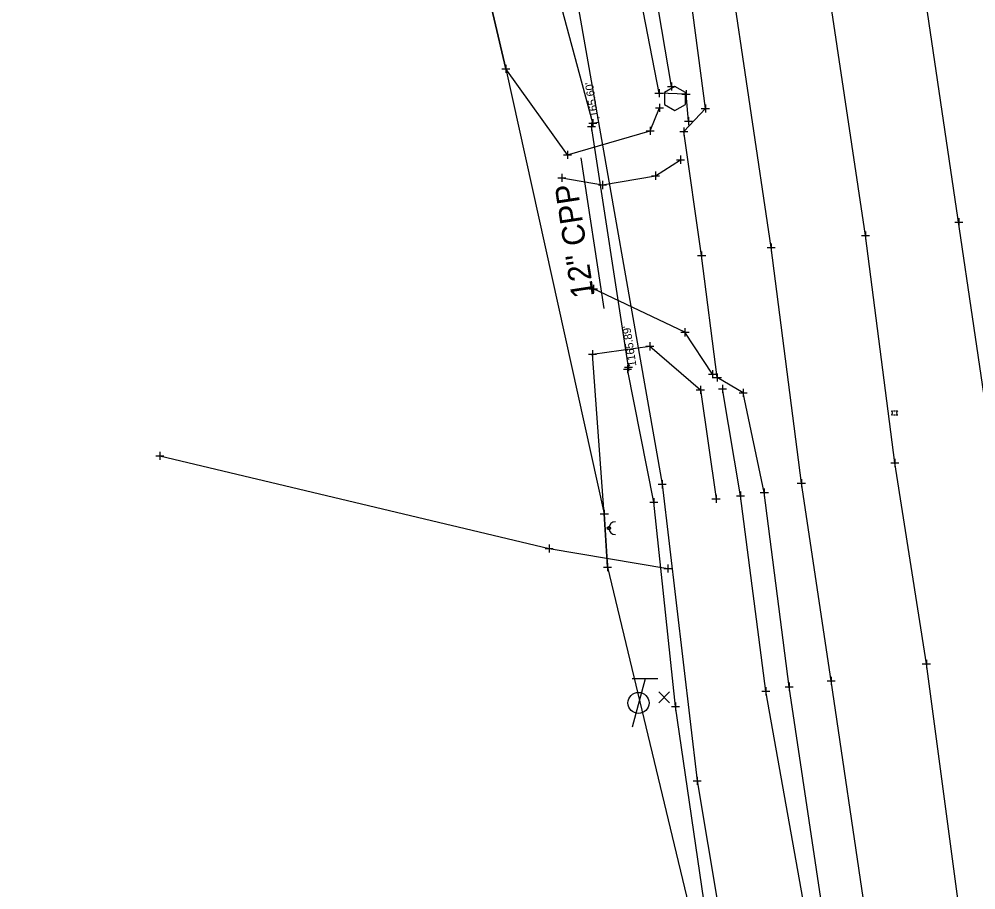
# Model space of a CAD drawing. Extents: x 2324380 to 2325559, y 691096 to 693386.
# Drawn here: x 2325087.6 to 2325205.9, y 691550.8 to 691658.5 of the extents above; entities that cross this region are included whole.
import ezdxf

# ---------------------------------------------------------------- set-up
doc = ezdxf.new("R2010")
doc.units = 0
for name, color, linetype in [('DR_X_Elev_Flow', 7, 'Continuous'), ('DR_X_Storm_Sewer', 7, 'Continuous'), ('DR_X_Text', 7, 'Continuous'), ('PM_X_Cells', 7, 'Continuous'), ('PM_X_CL_Double_Solid', 7, 'Continuous'), ('PM_X_Transverse_Line', 7, 'Continuous'), ('PV_X_COP', 7, 'Continuous'), ('PV_X_Driveway', 7, 'Continuous'), ('PV_X_EOP', 7, 'Continuous'), ('PV_X_Shoulder_Aggregate', 7, 'Continuous'), ('RD_X_Cells', 7, 'Continuous'), ('RD_X_GR_Lt', 7, 'Continuous'), ('SC_Scratch1', 7, 'Continuous'), ('SV_X_Random_Point', 7, 'Continuous'), ('SV_X_Shot_Marker', 7, 'Continuous'), ('SV_X_Terrain_Boundary', 7, 'Continuous'), ('SV_X_Toe_of_Slope', 7, 'Continuous'), ('SV_X_Top_of_Bank', 7, 'Continuous'), ('UT_X_Gas', 7, 'Continuous'), ('UT_X_Misc_Cells', 7, 'Continuous'), ('UT_X_Telecom_Cells', 7, 'Continuous')]:
    doc.layers.add(name, color=color, linetype=linetype)

msp = doc.modelspace()

# ---------------------------------------------------------------- linework, layer by layer
at = {"layer": 'DR_X_Elev_Flow'}
for p, q in [((2325157.91, 691645.2), (2325158.91, 691645.2)), ((2325158.41, 691645.7), (2325158.41, 691644.7)), ((2325158.41, 691645.2), (2325158.41, 691645.2)), ((2325162.97, 691615.95), (2325162.97, 691614.95)), ((2325162.47, 691615.45), (2325163.47, 691615.45)), ((2325162.97, 691615.45), (2325162.97, 691615.45))]:
    msp.add_line(p, q, dxfattribs=at)
at = {"layer": 'DR_X_Storm_Sewer'}
msp.add_line((2325162.97, 691615.45), (2325158.41, 691645.2), dxfattribs=at)
at = {"layer": 'DR_X_Text'}
msp.add_line((2325157.08, 691641.34), (2325159.94, 691622.69), dxfattribs=at)
at = {"layer": 'PM_X_Cells'}
for p, q in [((2325195.49, 691610.02), (2325195.59, 691610.02)), ((2325195.66, 691610.02), (2325195.76, 691610.02)), ((2325195.83, 691610.02), (2325195.93, 691610.02)), ((2325195.88, 691609.78), (2325195.88, 691609.78)), ((2325196, 691610.02), (2325196.1, 691610.02)), ((2325196.16, 691610.02), (2325196.26, 691610.02)), ((2325195.49, 691609.53), (2325195.59, 691609.53)), ((2325195.66, 691609.53), (2325195.76, 691609.53)), ((2325195.83, 691609.53), (2325195.93, 691609.53)), ((2325196, 691609.53), (2325196.1, 691609.53)), ((2325196.16, 691609.53), (2325196.26, 691609.53))]:
    msp.add_line(p, q, dxfattribs=at)
for centre, start, end in [((2325195.34, 691609.78), 42.0847, 58.0262), ((2325195.34, 691609.78), 301.9738, 317.9205), ((2325195.34, 691609.78), 18.8878, 34.8207), ((2325195.34, 691609.78), 325.1782, 341.1111), ((2325195.34, 691609.78), 348.3904, 11.6202), ((2325196.42, 691609.78), 168.3816, 191.6091), ((2325196.42, 691609.78), 145.1782, 161.1098), ((2325196.42, 691609.78), 198.8872, 214.8207), ((2325196.42, 691609.78), 121.9738, 137.9163), ((2325196.42, 691609.78), 222.0817, 238.0262)]:
    msp.add_arc(centre, 0.288, start, end, dxfattribs=at)
at = {"layer": 'PM_X_CL_Double_Solid'}
msp.add_lwpolyline([(2325203.69, 691549.65), (2325199.81, 691578.72), (2325195.9, 691603.62), (2325192.28, 691631.74), (2325187.11, 691666.48), (2325182.79, 691692.39), (2325178.74, 691718.23), (2325173.96, 691747.27), (2325169.08, 691775.55), (2325163.39, 691807.62), (2325158.37, 691834.22), (2325153.07, 691860.53), (2325147.82, 691885.48), (2325142.33, 691910.37), (2325135.95, 691937.62), (2325128.86, 691967.59), (2325122.12, 691994.31), (2325114.33, 692023.68), (2325108.45, 692046.03), (2325104.94, 692058.15)], dxfattribs=at)
at = {"layer": 'PM_X_Transverse_Line'}
for points in [[(2325208.03, 691604.62), (2325194.77, 691694.59), (2325190.22, 691721.35), (2325186.04, 691748.47), (2325180.66, 691777.72), (2325175.44, 691810.81), (2325170.12, 691836.61), (2325164.91, 691862.73), (2325159.59, 691887.99), (2325154.32, 691913.69), (2325148, 691940.38), (2325141.01, 691970.75), (2325134.25, 691997.6), (2325126.61, 692026.24), (2325119.99, 692049.57), (2325112.24, 692077.64)], [(2325192.19, 691548.44), (2325188.05, 691576.64), (2325184.35, 691601.09), (2325180.61, 691630.23), (2325175.41, 691665.27), (2325167.04, 691716.76), (2325162.47, 691745.62), (2325157.37, 691774.04), (2325151.47, 691805.52), (2325146.76, 691831.27), (2325141.02, 691858.38), (2325136.15, 691882.66), (2325130.6, 691908), (2325124.67, 691934.37), (2325117.5, 691964.78), (2325110.75, 691991.5), (2325102.89, 692021.66), (2325098.58, 692037.21)]]:
    msp.add_lwpolyline(points, dxfattribs=at)
at = {"layer": 'PV_X_COP'}
msp.add_lwpolyline([(2325203.69, 691549.65), (2325199.81, 691578.72), (2325195.9, 691603.62), (2325192.28, 691631.74), (2325187.11, 691666.48), (2325182.79, 691692.39), (2325178.74, 691718.23), (2325173.96, 691747.27), (2325169.08, 691775.55), (2325163.39, 691807.62), (2325158.37, 691834.22), (2325153.07, 691860.53), (2325147.82, 691885.48), (2325142.33, 691910.37), (2325135.95, 691937.62), (2325128.86, 691967.59), (2325122.12, 691994.31), (2325114.33, 692023.68), (2325108.45, 692046.03), (2325099.34, 692075.66)], dxfattribs=at)
at = {"layer": 'PV_X_Driveway'}
for points in [[(2325154.73, 691638.85), (2325159.77, 691637.98), (2325166.32, 691639.13), (2325169.41, 691641.11)], [(2325173.37, 691614.57), (2325169.96, 691619.75), (2325158.63, 691625.14)]]:
    msp.add_lwpolyline(points, dxfattribs=at)
at = {"layer": 'PV_X_EOP'}
for p, q in [((2325172.48, 691647.45), (2325170.28, 691664.36)), ((2325169.81, 691644.61), (2325172.48, 691647.45)), ((2325172.02, 691629.24), (2325169.81, 691644.61)), ((2325173.96, 691614.17), (2325172.02, 691629.24)), ((2325177.16, 691612.27), (2325173.96, 691614.17)), ((2325179.77, 691599.94), (2325177.16, 691612.27)), ((2325182.84, 691575.91), (2325179.77, 691599.94)), ((2325187.12, 691547.4), (2325182.84, 691575.91))]:
    msp.add_line(p, q, dxfattribs=at)
at = {"layer": 'PV_X_Shoulder_Aggregate'}
for points in [[(2325170.4, 691645.86), (2325170.09, 691649.23), (2325166.75, 691649.33), (2325163.95, 691663.81), (2325159.46, 691688.82), (2325155.24, 691715.43), (2325150.26, 691742.78), (2325145.57, 691771.72), (2325140.06, 691803.19), (2325135.21, 691830.02), (2325129.98, 691855.68), (2325124.5, 691880.26), (2325119.34, 691905.48), (2325112.99, 691932.07), (2325105.49, 691961.94), (2325098.55, 691989.12), (2325091.91, 692018.77), (2325090.18, 692026), (2325093.94, 692028.55)], [(2325216.93, 691320.12), (2325213.13, 691346.45), (2325209.2, 691372.56), (2325204.44, 691403.48), (2325200.05, 691432.7), (2325196.09, 691464.3), (2325192.26, 691490.46), (2325188.82, 691516.64), (2325184.99, 691547.18), (2325179.95, 691575.34), (2325176.82, 691599.54), (2325174.6, 691612.75)]]:
    msp.add_lwpolyline(points, dxfattribs=at)
at = {"layer": 'RD_X_Cells'}
msp.add_lwpolyline([(2325167.41, 691647.93), (2325168.71, 691647.18), (2325170.01, 691647.93), (2325170.01, 691649.43), (2325168.71, 691650.18), (2325167.41, 691649.43), (2325167.41, 691647.93)], dxfattribs=at)
at = {"layer": 'RD_X_GR_Lt'}
msp.add_lwpolyline([(2325168.31, 691650.15), (2325165.91, 691664.32), (2325160.24, 691688.12), (2325157.53, 691715.74), (2325153.07, 691743.32), (2325148.21, 691772.69), (2325142.47, 691803.42), (2325137.57, 691830.35), (2325132.48, 691855.68), (2325127.08, 691880.89), (2325121.34, 691906.57), (2325115.7, 691932.5), (2325101.27, 691989.61), (2325092.98, 692018.84), (2325091.76, 692024.72)], dxfattribs=at)
at = {"layer": 'SV_X_Random_Point'}
for p, q in [((2325166.72, 691573.93), (2325168.06, 691575.26)), ((2325166.72, 691575.26), (2325168.06, 691573.93))]:
    msp.add_line(p, q, dxfattribs=at)
at = {"layer": 'SV_X_Shot_Marker'}
for p, q in [((2325147.29, 691652.35), (2325148.29, 691652.35)), ((2325147.79, 691652.85), (2325147.79, 691651.85)), ((2325147.79, 691652.35), (2325147.79, 691652.35)), ((2325166.75, 691649.83), (2325166.75, 691648.83)), ((2325167.81, 691650.15), (2325168.81, 691650.15)), ((2325168.31, 691650.65), (2325168.31, 691649.65)), ((2325168.31, 691650.15), (2325168.31, 691650.15)), ((2325166.25, 691649.33), (2325167.25, 691649.33)), ((2325166.75, 691649.33), (2325166.75, 691649.33)), ((2325169.59, 691649.23), (2325170.59, 691649.23)), ((2325170.09, 691649.73), (2325170.09, 691648.73)), ((2325170.09, 691649.23), (2325170.09, 691649.23)), ((2325166.32, 691647.53), (2325167.32, 691647.53)), ((2325166.82, 691648.03), (2325166.82, 691647.03)), ((2325166.82, 691647.53), (2325166.82, 691647.53)), ((2325171.98, 691647.45), (2325172.98, 691647.45)), ((2325172.48, 691647.95), (2325172.48, 691646.95)), ((2325172.48, 691647.45), (2325172.48, 691647.45)), ((2325170.4, 691646.36), (2325170.4, 691645.36)), ((2325158.06, 691645.64), (2325159.06, 691645.64)), ((2325158.56, 691646.14), (2325158.56, 691645.14)), ((2325158.56, 691645.64), (2325158.56, 691645.64)), ((2325165.66, 691645.17), (2325165.66, 691644.17)), ((2325169.81, 691645.11), (2325169.81, 691644.11)), ((2325169.9, 691645.86), (2325170.9, 691645.86)), ((2325170.4, 691645.86), (2325170.4, 691645.86)), ((2325165.16, 691644.67), (2325166.16, 691644.67)), ((2325165.66, 691644.67), (2325165.66, 691644.67)), ((2325169.31, 691644.61), (2325170.31, 691644.61)), ((2325169.81, 691644.61), (2325169.81, 691644.61)), ((2325154.94, 691641.7), (2325155.94, 691641.7)), ((2325154.94, 691641.7), (2325155.94, 691641.7)), ((2325155.44, 691642.2), (2325155.44, 691641.2)), ((2325155.44, 691642.2), (2325155.44, 691641.2)), ((2325155.44, 691641.7), (2325155.44, 691641.7)), ((2325155.44, 691641.7), (2325155.44, 691641.7)), ((2325169.41, 691641.61), (2325169.41, 691640.61)), ((2325168.91, 691641.11), (2325169.91, 691641.11)), ((2325169.41, 691641.11), (2325169.41, 691641.11)), ((2325154.73, 691639.35), (2325154.73, 691638.35)), ((2325166.32, 691639.63), (2325166.32, 691638.63)), ((2325154.23, 691638.85), (2325155.23, 691638.85)), ((2325154.73, 691638.85), (2325154.73, 691638.85)), ((2325159.27, 691637.98), (2325160.27, 691637.98)), ((2325159.77, 691638.48), (2325159.77, 691637.48)), ((2325159.77, 691637.98), (2325159.77, 691637.98)), ((2325165.82, 691639.13), (2325166.82, 691639.13)), ((2325166.32, 691639.13), (2325166.32, 691639.13)), ((2325203.34, 691633.39), (2325204.34, 691633.39)), ((2325203.84, 691633.89), (2325203.84, 691632.89)), ((2325203.84, 691633.39), (2325203.84, 691633.39)), ((2325192.28, 691632.24), (2325192.28, 691631.24)), ((2325192.28, 691632.24), (2325192.28, 691631.24)), ((2325191.78, 691631.74), (2325192.78, 691631.74)), ((2325191.78, 691631.74), (2325192.78, 691631.74)), ((2325192.28, 691631.74), (2325192.28, 691631.74)), ((2325192.28, 691631.74), (2325192.28, 691631.74)), ((2325172.02, 691629.74), (2325172.02, 691628.74)), ((2325180.11, 691630.23), (2325181.11, 691630.23)), ((2325180.61, 691630.73), (2325180.61, 691629.73)), ((2325180.61, 691630.23), (2325180.61, 691630.23)), ((2325171.52, 691629.24), (2325172.52, 691629.24)), ((2325172.02, 691629.24), (2325172.02, 691629.24)), ((2325158.13, 691625.14), (2325159.13, 691625.14)), ((2325158.63, 691625.64), (2325158.63, 691624.64)), ((2325158.63, 691625.14), (2325158.63, 691625.14)), ((2325169.96, 691620.25), (2325169.96, 691619.25)), ((2325169.46, 691619.75), (2325170.46, 691619.75)), ((2325169.96, 691619.75), (2325169.96, 691619.75)), ((2325165.1, 691618.02), (2325166.1, 691618.02)), ((2325165.6, 691618.52), (2325165.6, 691617.52)), ((2325165.6, 691618.02), (2325165.6, 691618.02)), ((2325158.01, 691617.03), (2325159.01, 691617.03)), ((2325158.51, 691617.53), (2325158.51, 691616.53)), ((2325158.51, 691617.03), (2325158.51, 691617.03)), ((2325162.84, 691615.7), (2325162.84, 691614.7)), ((2325162.34, 691615.2), (2325163.34, 691615.2)), ((2325162.84, 691615.2), (2325162.84, 691615.2)), ((2325172.87, 691614.57), (2325173.87, 691614.57)), ((2325173.37, 691615.07), (2325173.37, 691614.07)), ((2325173.37, 691614.57), (2325173.37, 691614.57)), ((2325173.96, 691614.67), (2325173.96, 691613.67)), ((2325171.86, 691613.14), (2325171.86, 691612.14)), ((2325173.46, 691614.17), (2325174.46, 691614.17)), ((2325173.96, 691614.17), (2325173.96, 691614.17)), ((2325174.6, 691613.25), (2325174.6, 691612.25)), ((2325171.36, 691612.64), (2325172.36, 691612.64)), ((2325171.86, 691612.64), (2325171.86, 691612.64)), ((2325174.1, 691612.75), (2325175.1, 691612.75)), ((2325174.6, 691612.75), (2325174.6, 691612.75)), ((2325176.66, 691612.27), (2325177.66, 691612.27)), ((2325177.16, 691612.77), (2325177.16, 691611.77)), ((2325177.16, 691612.27), (2325177.16, 691612.27)), ((2325105.02, 691604.97), (2325105.02, 691603.97)), ((2325104.52, 691604.47), (2325105.52, 691604.47)), ((2325105.02, 691604.47), (2325105.02, 691604.47)), ((2325195.9, 691604.12), (2325195.9, 691603.12)), ((2325195.9, 691604.12), (2325195.9, 691603.12)), ((2325195.4, 691603.62), (2325196.4, 691603.62)), ((2325195.4, 691603.62), (2325196.4, 691603.62)), ((2325195.9, 691603.62), (2325195.9, 691603.62)), ((2325195.9, 691603.62), (2325195.9, 691603.62)), ((2325167.15, 691601.45), (2325167.15, 691600.45)), ((2325184.35, 691601.59), (2325184.35, 691600.59)), ((2325166.65, 691600.95), (2325167.65, 691600.95)), ((2325167.15, 691600.95), (2325167.15, 691600.95)), ((2325179.77, 691600.44), (2325179.77, 691599.44)), ((2325183.85, 691601.09), (2325184.85, 691601.09)), ((2325184.35, 691601.09), (2325184.35, 691601.09)), ((2325166.12, 691599.25), (2325166.12, 691598.25)), ((2325173.3, 691599.14), (2325174.3, 691599.14)), ((2325173.8, 691599.64), (2325173.8, 691598.64)), ((2325173.8, 691599.14), (2325173.8, 691599.14)), ((2325176.32, 691599.54), (2325177.32, 691599.54)), ((2325176.82, 691600.04), (2325176.82, 691599.04)), ((2325176.82, 691599.54), (2325176.82, 691599.54)), ((2325179.27, 691599.94), (2325180.27, 691599.94)), ((2325179.77, 691599.94), (2325179.77, 691599.94)), ((2325159.98, 691597.81), (2325159.98, 691596.81)), ((2325165.62, 691598.75), (2325166.62, 691598.75)), ((2325166.12, 691598.75), (2325166.12, 691598.75)), ((2325159.48, 691597.31), (2325160.48, 691597.31)), ((2325159.98, 691597.31), (2325159.98, 691597.31)), ((2325152.65, 691593), (2325153.65, 691593)), ((2325153.15, 691593.5), (2325153.15, 691592.5)), ((2325153.15, 691593), (2325153.15, 691593)), ((2325159.88, 691590.71), (2325160.88, 691590.71)), ((2325160.38, 691591.21), (2325160.38, 691590.21)), ((2325160.38, 691590.71), (2325160.38, 691590.71)), ((2325167.85, 691591.04), (2325167.85, 691590.04)), ((2325167.35, 691590.54), (2325168.35, 691590.54)), ((2325167.85, 691590.54), (2325167.85, 691590.54)), ((2325199.81, 691579.22), (2325199.81, 691578.22)), ((2325199.81, 691579.22), (2325199.81, 691578.22)), ((2325199.31, 691578.72), (2325200.31, 691578.72)), ((2325199.31, 691578.72), (2325200.31, 691578.72)), ((2325199.81, 691578.72), (2325199.81, 691578.72)), ((2325199.81, 691578.72), (2325199.81, 691578.72)), ((2325187.55, 691576.64), (2325188.55, 691576.64)), ((2325188.05, 691577.14), (2325188.05, 691576.14)), ((2325188.05, 691576.64), (2325188.05, 691576.64)), ((2325179.45, 691575.34), (2325180.45, 691575.34)), ((2325179.95, 691575.84), (2325179.95, 691574.84)), ((2325179.95, 691575.34), (2325179.95, 691575.34)), ((2325182.34, 691575.91), (2325183.34, 691575.91)), ((2325182.84, 691576.41), (2325182.84, 691575.41)), ((2325182.84, 691575.91), (2325182.84, 691575.91)), ((2325168.3, 691573.47), (2325169.3, 691573.47)), ((2325168.8, 691573.97), (2325168.8, 691572.97)), ((2325168.8, 691573.47), (2325168.8, 691573.47)), ((2325171.48, 691564.76), (2325171.48, 691563.76)), ((2325170.98, 691564.26), (2325171.98, 691564.26)), ((2325171.48, 691564.26), (2325171.48, 691564.26))]:
    msp.add_line(p, q, dxfattribs=at)
at = {"layer": 'SV_X_Terrain_Boundary'}
msp.add_lwpolyline([(2324706.09, 691698.67), (2324706.18, 691695.88), (2324786.83, 691704.47), (2324881.61, 691710.43), (2324976.22, 691742.08), (2325077, 691767.97), (2325139.81, 691686.44), (2325147.79, 691652.35), (2325159.98, 691597.31), (2325160.38, 691590.71), (2325171.14, 691545.87)], dxfattribs=at)
at = {"layer": 'SV_X_Toe_of_Slope'}
for points in [[(2325158.56, 691645.64), (2325147.08, 691688.36), (2325134.23, 691743.21), (2325125.58, 691792.13), (2325129.38, 691804.3), (2325075.41, 691780.38)], [(2325213.6, 691319.64), (2325209.11, 691346.45), (2325200.62, 691370.89), (2325198.94, 691401.86), (2325189.24, 691430.45), (2325184.74, 691463.91), (2325180.93, 691488.53), (2325177.21, 691514.2), (2325172.8, 691546.11), (2325168.8, 691573.47), (2325166.12, 691598.75), (2325162.84, 691615.2)]]:
    msp.add_lwpolyline(points, dxfattribs=at)
at = {"layer": 'SV_X_Top_of_Bank'}
for points in [[(2325155.44, 691641.7), (2325147.79, 691652.35), (2325139.81, 691686.44), (2325127.05, 691741.13), (2325119.28, 691790.45), (2325077, 691767.97)], [(2325155.44, 691641.7), (2325165.66, 691644.67), (2325166.82, 691647.53)], [(2325160.38, 691590.71), (2325159.98, 691597.31), (2325158.51, 691617.03), (2325165.6, 691618.02), (2325171.86, 691612.64), (2325173.8, 691599.14)]]:
    msp.add_lwpolyline(points, dxfattribs=at)
at = {"layer": 'UT_X_Gas'}
for points in [[(2324989.07, 691970.86), (2325011.6, 691941.58), (2325048.05, 691885.65), (2325093.46, 691823.6), (2325120.8, 691783.81), (2325138.43, 691746.33), (2325151.4, 691693.8), (2325156.77, 691659.76), (2325167.15, 691600.95), (2325171.48, 691564.26), (2325179.43, 691516.76), (2325185.5, 691470.97), (2325191.97, 691423.91), (2325198.27, 691377.48), (2325205.02, 691332.94), (2325213.79, 691283.13)], [(2325105.02, 691604.47), (2325153.15, 691593), (2325167.85, 691590.54)]]:
    msp.add_lwpolyline(points, dxfattribs=at)
at = {"layer": 'UT_X_Misc_Cells'}
msp.add_circle((2325160.55, 691595.52), 0.2, dxfattribs=at)
msp.add_arc((2325161.35, 691595.52), 0.8, 90, 270, dxfattribs=at)
at = {"layer": 'UT_X_Telecom_Cells'}
for p, q in [((2325165.02, 691576.9), (2325163.41, 691570.9)), ((2325166.62, 691576.9), (2325163.42, 691576.9))]:
    msp.add_line(p, q, dxfattribs=at)
msp.add_circle((2325164.21, 691573.9), 1.3, dxfattribs=at)

# ---------------------------------------------------------------- texts
at = {"layer": 'DR_X_Text'}
msp.add_text('12" CPP', height=2.8, rotation=98.7235, dxfattribs=at).set_placement((2325158.75, 691624.22))
at = {"layer": 'SC_Scratch1'}
for s, p in [("1,165.60'", (2325159.39, 691645.35)), ("1165.89'", (2325163.96, 691615.6))]:
    msp.add_text(s, height=1, rotation=98.7235, dxfattribs=at).set_placement(p)

doc.saveas('drawing.dxf')
